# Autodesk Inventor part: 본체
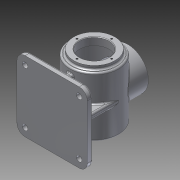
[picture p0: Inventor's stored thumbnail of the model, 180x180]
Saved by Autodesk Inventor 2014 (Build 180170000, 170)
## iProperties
Created: 2015-07
Part Number: 본체
Material: 알루미늄 6061
Document SubType Name: Modeling
Designer: Owner
Density: 2.71 g/cm^3
Mass: 1277.62 g
Surface Area: 1267.64 cm^2
Volume: 471.447 cm^3
Appearance: 알루미늄 - 평지
Author: Owner
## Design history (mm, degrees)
sketch "스케치1"
  geometry: C1 r 45 at (0, 0); 1 further point
  constraints: 1 centre point, 1 coincident
  dimensions: "d0" = 90 diameter of C1
extrude "돌출1" new body sketch "스케치1" stored distance "d1" = 110; taper "d2" = 0 deg
sketch "스케치2"
  geometry: C1 r 45 at (0, 0) reference; C2 r 38 at (0, 0)
  constraints: 1 centre point, 1 coincident
  dimensions: "d3" = 76 diameter of C2
extrude "돌출2" join sketch "스케치2" distance "d4" = 7; taper "d5" = 0 deg
sketch "스케치3"
  geometry: C1 r 40 at (0, 0); 1 further point
  constraints: 1 centre point, 1 coincident
  dimensions: "d6" = 80 diameter of C1
extrude "돌출3" cut sketch "스케치3" stored distance "d7" = 96; taper "d8" = 0 deg
sketch "스케치4"
  geometry: C1 r 38 at (0, 0) reference; C2 r 27 at (0, 0)
  constraints: 1 centre point, 1 coincident
  dimensions: "d9" = 54 diameter of C2
extrude "돌출4" cut sketch "스케치4" stored distance "d10" = 96; taper "d11" = 0 deg
node "작업 평면1"
sketch "스케치5"
  geometry: L1 (65, 65)-(-65, 65); L2 (-65, 65)-(-65, -65); L3 (-65, -65)-(65, -65); L4 (65, -65)-(65, 65); L5 (65, -65)-(-65, 65); L6 (65, 65)-(-65, -65); 2 further points
  constraints: 12 end point, 2 parallel, 1 coincident, 1 horizontal, 1 midpoint, 1 perpendicular
  dimensions: "d13" = 130 distance of L3.end L2.end; "d14" = 130 distance of L2.end L1.end
extrude "돌출5" join sketch "스케치5" distance "d15" = 10; taper "d16" = 0 deg
sketch "스케치6"
  geometry: L1 (45, 0)-(45, -68); L2 (-45, 0)-(-45, -68); L3 (-65, -68)-(65, -68) reference; A1 r 45 centre (0, 0) between (-45, 0) and (45, 0) reference; 1 further point
  constraints: 4 end point, 2 point on circle, 2 point on line, 2 tangent, 1 parallel, 1 vertical
extrude "돌출6" join sketch "스케치6" stored distance "d17" = 10; taper "d18" = 0 deg
fillet "모깎기1" dims "d23" = 15
node "작업 평면2"
sketch "스케치8"
  geometry: C1 r 38 at (0, 0); 1 further point
  constraints: 1 centre point, 1 coincident
  dimensions: "d25" = 76 diameter of C1
extrude "돌출8" join sketch "스케치8" stored distance "d26" = 10; taper "d27" = 0 deg
sketch "스케치9"
  geometry: C1 r 27 at (0, 0); 1 further point
  constraints: 1 centre point, 1 coincident
  dimensions: "d28" = 54 diameter of C1
extrude "돌출9" cut sketch "스케치9" stored distance "d29" = 10; taper "d30" = 0 deg
sketch "스케치10"
  geometry: 2 further points
  constraints: 1 horizontal alignment
  dimensions: "d31" = 32 distance of point (0, 0) point (-32, 0)
hole "구멍1" sketch "스케치10" at (-32, 0) diameter "d32" = 3.242; stored, may be unused: countersink angle "d36" = 90 deg, drill point angle "d38" = 118 deg; dims "d33" = 8, "d34" = 4, "d35" = 2, "d37" = 10
sketch "스케치11"
  geometry: C1 r 27 at (0, 0) reference; 1 further point
  constraints: 1 vertical alignment
  dimensions: "d42" = 32 distance of C1.centre point (0, 32)
hole "구멍2" sketch "스케치11" at (0, 32) diameter "d43" = 3.242; stored, may be unused: countersink angle "d47" = 90 deg, drill point angle "d49" = 118 deg; dims "d44" = 8, "d45" = 4, "d46" = 2, "d48" = 10
sketch "스케치12"
  geometry: C1 r 7.5 at (-50, 50); A1 r 15 centre (-50, 50) between (-50, 65) and (-65, 50) reference; 1 further point
  constraints: 1 centre point, 1 coincident
  dimensions: "d53" = 15 diameter of C1
extrude "돌출10" join sketch "스케치12" distance "d54" = 3; taper "d55" = 0 deg
sketch "스케치13"
  geometry: C1 r 7.5 at (0, 0) reference; C2 r 5 at (0, 0); 1 further point
  constraints: 1 centre point, 1 coincident
  dimensions: "d56" = 10 diameter of C2
extrude "돌출11" cut sketch "스케치13" stored distance "d57" = 3; taper "d58" = 0 deg
fillet "모깎기2" dims "d59" = 3
chamfer "모따기1" distance "d66" = 1; stored, may be unused: second distance "d67" = 2, angle "d68" = 45 deg
fillet "모깎기3" dims "d69" = 3
fillet "모깎기4" dims "d70" = 3
sketch "스케치14"
  geometry: L1 (-5, 45)-(5, 45); L2 (5, 45)-(5, -45); L3 (5, -45)-(-5, -45); L4 (-5, -45)-(-5, 45); L5 (-5, 45)-(5, -45); 2 further points
  constraints: 10 end point, 2 parallel, 1 coincident, 1 horizontal, 1 midpoint, 1 perpendicular
  dimensions: "d71" = 10 distance of L1.start L1.end; "d72" = 90 distance of L3.end L1.start
extrude "돌출12" join sketch "스케치14" stored distance "d73" = 3; taper "d74" = 0 deg
fillet "모깎기5" dims "d75" = 3
fillet "모깎기6" dims "d76" = 3
fillet "모깎기7" dims "d77" = 3
sketch "스케치15"
  geometry: C1 r 42 at (0, 0) reference; 2 further points
  constraints: 3 coincident, 1 other
feature "엠보싱1" sketch "스케치15" dims "d78" = 0.5, "d79" = 0
fillet "모깎기8" dims "d80" = 3
fillet "모깎기9" dims "d81" = 3
node "솔리드1"
pattern_circular "원형 패턴1" dims angle "d40" = 360 deg
pattern_circular "원형 패턴2" dims angle "d51" = 360 deg
pattern_linear "직사각형 패턴1"
other parameters: "d12" = -78
